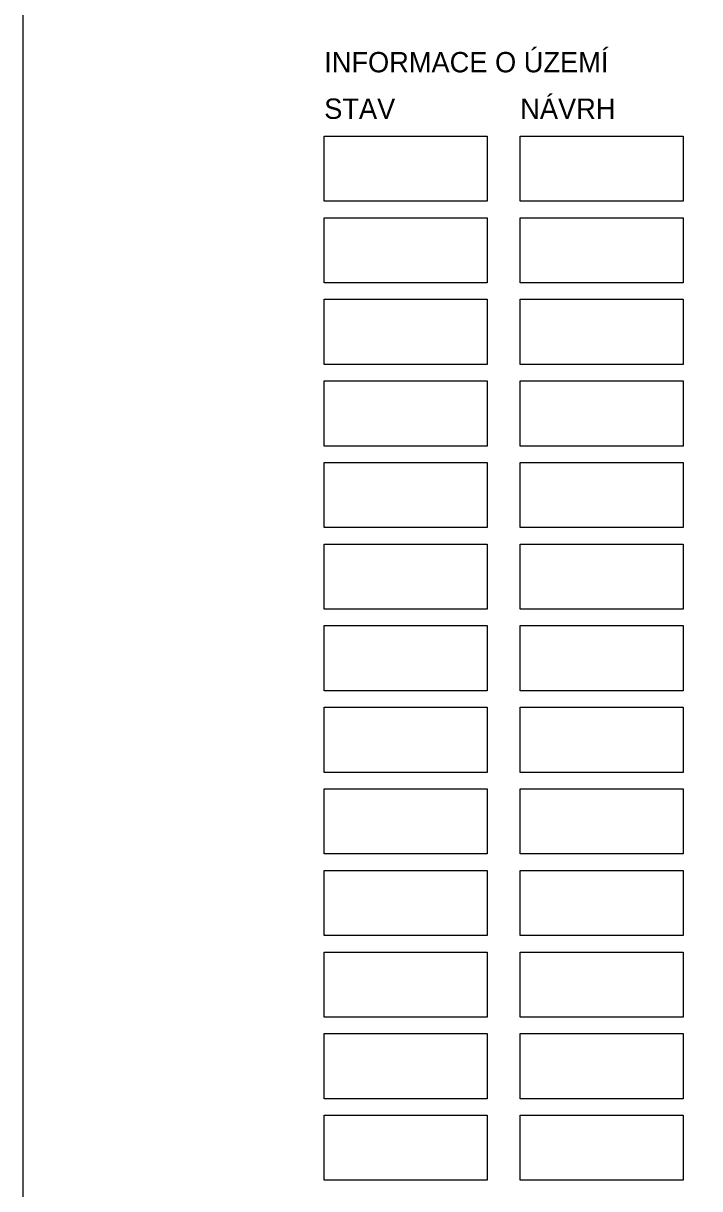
# Model space of a CAD drawing. Extents: x -443494 to -430443, y -1146902 to -1140081.
# Drawn here: x -436490 to -436058, y -1142374 to -1141630 of the extents above; entities that cross this region are included whole.
import ezdxf

# ---------------------------------------------------------------- set-up
doc = ezdxf.new("R2010")
doc.units = 0
doc.layers.add('Vrstva 1', color=7, linetype='Continuous')

msp = doc.modelspace()

# ---------------------------------------------------------------- linework, layer by layer
at = {"layer": 'Vrstva 1'}
for points in [[(-433990.008, -1140080.76), (-433990.008, -1143080.76), (-436490.008, -1143080.76), (-436490.008, -1140080.76)], [(-436297.845, -1141701.798), (-436193.845, -1141701.798), (-436193.845, -1141743.398), (-436297.845, -1141743.398)], [(-436297.845, -1141701.798), (-436193.845, -1141701.798), (-436193.845, -1141743.398), (-436297.845, -1141743.398)], [(-436297.845, -1141701.798), (-436193.845, -1141701.798), (-436193.845, -1141743.398), (-436297.845, -1141743.398)], [(-436297.845, -1141701.798), (-436193.845, -1141701.798), (-436193.845, -1141743.398), (-436297.845, -1141743.398)], [(-436297.845, -1141701.798), (-436193.845, -1141701.798), (-436193.845, -1141743.398), (-436297.845, -1141743.398)], [(-436297.845, -1141701.798), (-436193.845, -1141701.798), (-436193.845, -1141743.398), (-436297.845, -1141743.398)], [(-436297.845, -1141701.798), (-436193.845, -1141701.798), (-436193.845, -1141743.398), (-436297.845, -1141743.398)], [(-436297.845, -1141701.798), (-436193.845, -1141701.798), (-436193.845, -1141743.398), (-436297.845, -1141743.398)], [(-436172.653, -1141701.798), (-436068.653, -1141701.798), (-436068.653, -1141743.398), (-436172.653, -1141743.398)], [(-436172.653, -1141701.798), (-436068.653, -1141701.798), (-436068.653, -1141743.398), (-436172.653, -1141743.398)], [(-436172.653, -1141701.798), (-436068.653, -1141701.798), (-436068.653, -1141743.398), (-436172.653, -1141743.398)], [(-436172.653, -1141701.798), (-436068.653, -1141701.798), (-436068.653, -1141743.398), (-436172.653, -1141743.398)], [(-436172.653, -1141701.798), (-436068.653, -1141701.798), (-436068.653, -1141743.398), (-436172.653, -1141743.398)], [(-436172.653, -1141701.798), (-436068.653, -1141701.798), (-436068.653, -1141743.398), (-436172.653, -1141743.398)], [(-436172.653, -1141701.798), (-436068.653, -1141701.798), (-436068.653, -1141743.398), (-436172.653, -1141743.398)], [(-436172.653, -1141701.798), (-436068.653, -1141701.798), (-436068.653, -1141743.398), (-436172.653, -1141743.398)], [(-436297.845, -1141753.888), (-436193.845, -1141753.888), (-436193.845, -1141795.488), (-436297.845, -1141795.488)], [(-436297.845, -1141753.888), (-436193.845, -1141753.888), (-436193.845, -1141795.488), (-436297.845, -1141795.488)], [(-436297.845, -1141753.888), (-436193.845, -1141753.888), (-436193.845, -1141795.488), (-436297.845, -1141795.488)], [(-436297.845, -1141753.888), (-436193.845, -1141753.888), (-436193.845, -1141795.488), (-436297.845, -1141795.488)], [(-436297.845, -1141753.888), (-436193.845, -1141753.888), (-436193.845, -1141795.488), (-436297.845, -1141795.488)], [(-436297.845, -1141753.888), (-436193.845, -1141753.888), (-436193.845, -1141795.488), (-436297.845, -1141795.488)], [(-436297.845, -1141753.888), (-436193.845, -1141753.888), (-436193.845, -1141795.488), (-436297.845, -1141795.488)], [(-436297.845, -1141753.888), (-436193.845, -1141753.888), (-436193.845, -1141795.488), (-436297.845, -1141795.488)], [(-436172.653, -1141753.888), (-436068.653, -1141753.888), (-436068.653, -1141795.488), (-436172.653, -1141795.488)], [(-436172.653, -1141753.888), (-436068.653, -1141753.888), (-436068.653, -1141795.488), (-436172.653, -1141795.488)], [(-436172.653, -1141753.888), (-436068.653, -1141753.888), (-436068.653, -1141795.488), (-436172.653, -1141795.488)], [(-436172.653, -1141753.888), (-436068.653, -1141753.888), (-436068.653, -1141795.488), (-436172.653, -1141795.488)], [(-436172.653, -1141753.888), (-436068.653, -1141753.888), (-436068.653, -1141795.488), (-436172.653, -1141795.488)], [(-436172.653, -1141753.888), (-436068.653, -1141753.888), (-436068.653, -1141795.488), (-436172.653, -1141795.488)], [(-436172.653, -1141753.888), (-436068.653, -1141753.888), (-436068.653, -1141795.488), (-436172.653, -1141795.488)], [(-436172.653, -1141753.888), (-436068.653, -1141753.888), (-436068.653, -1141795.488), (-436172.653, -1141795.488)], [(-436297.845, -1141805.98), (-436193.845, -1141805.98), (-436193.845, -1141847.58), (-436297.845, -1141847.58)], [(-436297.845, -1141805.98), (-436193.845, -1141805.98), (-436193.845, -1141847.58), (-436297.845, -1141847.58)], [(-436297.845, -1141805.98), (-436193.845, -1141805.98), (-436193.845, -1141847.58), (-436297.845, -1141847.58)], [(-436297.845, -1141805.98), (-436193.845, -1141805.98), (-436193.845, -1141847.58), (-436297.845, -1141847.58)], [(-436297.845, -1141805.98), (-436193.845, -1141805.98), (-436193.845, -1141847.58), (-436297.845, -1141847.58)], [(-436297.845, -1141805.98), (-436193.845, -1141805.98), (-436193.845, -1141847.58), (-436297.845, -1141847.58)], [(-436297.845, -1141805.98), (-436193.845, -1141805.98), (-436193.845, -1141847.58), (-436297.845, -1141847.58)], [(-436297.845, -1141805.98), (-436193.845, -1141805.98), (-436193.845, -1141847.58), (-436297.845, -1141847.58)], [(-436172.653, -1141805.98), (-436068.653, -1141805.98), (-436068.653, -1141847.58), (-436172.653, -1141847.58)], [(-436172.653, -1141805.98), (-436068.653, -1141805.98), (-436068.653, -1141847.58), (-436172.653, -1141847.58)], [(-436172.653, -1141805.98), (-436068.653, -1141805.98), (-436068.653, -1141847.58), (-436172.653, -1141847.58)], [(-436172.653, -1141805.98), (-436068.653, -1141805.98), (-436068.653, -1141847.58), (-436172.653, -1141847.58)], [(-436172.653, -1141805.98), (-436068.653, -1141805.98), (-436068.653, -1141847.58), (-436172.653, -1141847.58)], [(-436172.653, -1141805.98), (-436068.653, -1141805.98), (-436068.653, -1141847.58), (-436172.653, -1141847.58)], [(-436172.653, -1141805.98), (-436068.653, -1141805.98), (-436068.653, -1141847.58), (-436172.653, -1141847.58)], [(-436172.653, -1141805.98), (-436068.653, -1141805.98), (-436068.653, -1141847.58), (-436172.653, -1141847.58)], [(-436297.845, -1141858.072), (-436193.845, -1141858.072), (-436193.845, -1141899.672), (-436297.845, -1141899.672)], [(-436297.845, -1141858.072), (-436193.845, -1141858.072), (-436193.845, -1141899.672), (-436297.845, -1141899.672)], [(-436297.845, -1141858.072), (-436193.845, -1141858.072), (-436193.845, -1141899.672), (-436297.845, -1141899.672)], [(-436297.845, -1141858.072), (-436193.845, -1141858.072), (-436193.845, -1141899.672), (-436297.845, -1141899.672)], [(-436297.845, -1141858.072), (-436193.845, -1141858.072), (-436193.845, -1141899.672), (-436297.845, -1141899.672)], [(-436297.845, -1141858.072), (-436193.845, -1141858.072), (-436193.845, -1141899.672), (-436297.845, -1141899.672)], [(-436297.845, -1141858.072), (-436193.845, -1141858.072), (-436193.845, -1141899.672), (-436297.845, -1141899.672)], [(-436297.845, -1141858.072), (-436193.845, -1141858.072), (-436193.845, -1141899.672), (-436297.845, -1141899.672)], [(-436172.653, -1141858.072), (-436068.653, -1141858.072), (-436068.653, -1141899.672), (-436172.653, -1141899.672)], [(-436172.653, -1141858.072), (-436068.653, -1141858.072), (-436068.653, -1141899.672), (-436172.653, -1141899.672)], [(-436172.653, -1141858.072), (-436068.653, -1141858.072), (-436068.653, -1141899.672), (-436172.653, -1141899.672)], [(-436172.653, -1141858.072), (-436068.653, -1141858.072), (-436068.653, -1141899.672), (-436172.653, -1141899.672)], [(-436172.653, -1141858.072), (-436068.653, -1141858.072), (-436068.653, -1141899.672), (-436172.653, -1141899.672)], [(-436172.653, -1141858.072), (-436068.653, -1141858.072), (-436068.653, -1141899.672), (-436172.653, -1141899.672)], [(-436172.653, -1141858.072), (-436068.653, -1141858.072), (-436068.653, -1141899.672), (-436172.653, -1141899.672)], [(-436172.653, -1141858.072), (-436068.653, -1141858.072), (-436068.653, -1141899.672), (-436172.653, -1141899.672)], [(-436297.845, -1141910.164), (-436193.845, -1141910.164), (-436193.845, -1141951.764), (-436297.845, -1141951.764)], [(-436297.845, -1141910.164), (-436193.845, -1141910.164), (-436193.845, -1141951.764), (-436297.845, -1141951.764)], [(-436297.845, -1141910.164), (-436193.845, -1141910.164), (-436193.845, -1141951.764), (-436297.845, -1141951.764)], [(-436297.845, -1141910.164), (-436193.845, -1141910.164), (-436193.845, -1141951.764), (-436297.845, -1141951.764)], [(-436297.845, -1141910.164), (-436193.845, -1141910.164), (-436193.845, -1141951.764), (-436297.845, -1141951.764)], [(-436297.845, -1141910.164), (-436193.845, -1141910.164), (-436193.845, -1141951.764), (-436297.845, -1141951.764)], [(-436297.845, -1141910.164), (-436193.845, -1141910.164), (-436193.845, -1141951.764), (-436297.845, -1141951.764)], [(-436297.845, -1141910.164), (-436193.845, -1141910.164), (-436193.845, -1141951.764), (-436297.845, -1141951.764)], [(-436172.653, -1141910.164), (-436068.653, -1141910.164), (-436068.653, -1141951.764), (-436172.653, -1141951.764)], [(-436172.653, -1141910.164), (-436068.653, -1141910.164), (-436068.653, -1141951.764), (-436172.653, -1141951.764)], [(-436172.653, -1141910.164), (-436068.653, -1141910.164), (-436068.653, -1141951.764), (-436172.653, -1141951.764)], [(-436172.653, -1141910.164), (-436068.653, -1141910.164), (-436068.653, -1141951.764), (-436172.653, -1141951.764)], [(-436172.653, -1141910.164), (-436068.653, -1141910.164), (-436068.653, -1141951.764), (-436172.653, -1141951.764)], [(-436172.653, -1141910.164), (-436068.653, -1141910.164), (-436068.653, -1141951.764), (-436172.653, -1141951.764)], [(-436172.653, -1141910.164), (-436068.653, -1141910.164), (-436068.653, -1141951.764), (-436172.653, -1141951.764)], [(-436172.653, -1141910.164), (-436068.653, -1141910.164), (-436068.653, -1141951.764), (-436172.653, -1141951.764)], [(-436297.845, -1141962.254), (-436193.845, -1141962.254), (-436193.845, -1142003.854), (-436297.845, -1142003.854)], [(-436297.845, -1141962.254), (-436193.845, -1141962.254), (-436193.845, -1142003.854), (-436297.845, -1142003.854)], [(-436297.845, -1141962.254), (-436193.845, -1141962.254), (-436193.845, -1142003.854), (-436297.845, -1142003.854)], [(-436297.845, -1141962.254), (-436193.845, -1141962.254), (-436193.845, -1142003.854), (-436297.845, -1142003.854)], [(-436297.845, -1141962.254), (-436193.845, -1141962.254), (-436193.845, -1142003.854), (-436297.845, -1142003.854)], [(-436297.845, -1141962.254), (-436193.845, -1141962.254), (-436193.845, -1142003.854), (-436297.845, -1142003.854)], [(-436297.845, -1141962.254), (-436193.845, -1141962.254), (-436193.845, -1142003.854), (-436297.845, -1142003.854)], [(-436297.845, -1141962.254), (-436193.845, -1141962.254), (-436193.845, -1142003.854), (-436297.845, -1142003.854)], [(-436172.653, -1141962.254), (-436068.653, -1141962.254), (-436068.653, -1142003.854), (-436172.653, -1142003.854)], [(-436172.653, -1141962.254), (-436068.653, -1141962.254), (-436068.653, -1142003.854), (-436172.653, -1142003.854)], [(-436172.653, -1141962.254), (-436068.653, -1141962.254), (-436068.653, -1142003.854), (-436172.653, -1142003.854)], [(-436172.653, -1141962.254), (-436068.653, -1141962.254), (-436068.653, -1142003.854), (-436172.653, -1142003.854)], [(-436172.653, -1141962.254), (-436068.653, -1141962.254), (-436068.653, -1142003.854), (-436172.653, -1142003.854)], [(-436172.653, -1141962.254), (-436068.653, -1141962.254), (-436068.653, -1142003.854), (-436172.653, -1142003.854)], [(-436172.653, -1141962.254), (-436068.653, -1141962.254), (-436068.653, -1142003.854), (-436172.653, -1142003.854)], [(-436172.653, -1141962.254), (-436068.653, -1141962.254), (-436068.653, -1142003.854), (-436172.653, -1142003.854)], [(-436297.845, -1142014.346), (-436193.845, -1142014.346), (-436193.845, -1142055.946), (-436297.845, -1142055.946)], [(-436297.845, -1142014.346), (-436193.845, -1142014.346), (-436193.845, -1142055.946), (-436297.845, -1142055.946)], [(-436297.845, -1142014.346), (-436193.845, -1142014.346), (-436193.845, -1142055.946), (-436297.845, -1142055.946)], [(-436297.845, -1142014.346), (-436193.845, -1142014.346), (-436193.845, -1142055.946), (-436297.845, -1142055.946)], [(-436297.845, -1142014.346), (-436193.845, -1142014.346), (-436193.845, -1142055.946), (-436297.845, -1142055.946)], [(-436297.845, -1142014.346), (-436193.845, -1142014.346), (-436193.845, -1142055.946), (-436297.845, -1142055.946)], [(-436297.845, -1142014.346), (-436193.845, -1142014.346), (-436193.845, -1142055.946), (-436297.845, -1142055.946)], [(-436297.845, -1142014.346), (-436193.845, -1142014.346), (-436193.845, -1142055.946), (-436297.845, -1142055.946)], [(-436172.653, -1142014.346), (-436068.653, -1142014.346), (-436068.653, -1142055.946), (-436172.653, -1142055.946)], [(-436172.653, -1142014.346), (-436068.653, -1142014.346), (-436068.653, -1142055.946), (-436172.653, -1142055.946)], [(-436172.653, -1142014.346), (-436068.653, -1142014.346), (-436068.653, -1142055.946), (-436172.653, -1142055.946)], [(-436172.653, -1142014.346), (-436068.653, -1142014.346), (-436068.653, -1142055.946), (-436172.653, -1142055.946)], [(-436172.653, -1142014.346), (-436068.653, -1142014.346), (-436068.653, -1142055.946), (-436172.653, -1142055.946)], [(-436172.653, -1142014.346), (-436068.653, -1142014.346), (-436068.653, -1142055.946), (-436172.653, -1142055.946)], [(-436172.653, -1142014.346), (-436068.653, -1142014.346), (-436068.653, -1142055.946), (-436172.653, -1142055.946)], [(-436172.653, -1142014.346), (-436068.653, -1142014.346), (-436068.653, -1142055.946), (-436172.653, -1142055.946)], [(-436297.845, -1142066.438), (-436193.845, -1142066.438), (-436193.845, -1142108.038), (-436297.845, -1142108.038)], [(-436297.845, -1142066.438), (-436193.845, -1142066.438), (-436193.845, -1142108.038), (-436297.845, -1142108.038)], [(-436297.845, -1142066.438), (-436193.845, -1142066.438), (-436193.845, -1142108.038), (-436297.845, -1142108.038)], [(-436297.845, -1142066.438), (-436193.845, -1142066.438), (-436193.845, -1142108.038), (-436297.845, -1142108.038)], [(-436297.845, -1142066.438), (-436193.845, -1142066.438), (-436193.845, -1142108.038), (-436297.845, -1142108.038)], [(-436297.845, -1142066.438), (-436193.845, -1142066.438), (-436193.845, -1142108.038), (-436297.845, -1142108.038)], [(-436297.845, -1142066.438), (-436193.845, -1142066.438), (-436193.845, -1142108.038), (-436297.845, -1142108.038)], [(-436297.845, -1142066.438), (-436193.845, -1142066.438), (-436193.845, -1142108.038), (-436297.845, -1142108.038)], [(-436172.653, -1142066.438), (-436068.653, -1142066.438), (-436068.653, -1142108.038), (-436172.653, -1142108.038)], [(-436172.653, -1142066.438), (-436068.653, -1142066.438), (-436068.653, -1142108.038), (-436172.653, -1142108.038)], [(-436172.653, -1142066.438), (-436068.653, -1142066.438), (-436068.653, -1142108.038), (-436172.653, -1142108.038)], [(-436172.653, -1142066.438), (-436068.653, -1142066.438), (-436068.653, -1142108.038), (-436172.653, -1142108.038)], [(-436172.653, -1142066.438), (-436068.653, -1142066.438), (-436068.653, -1142108.038), (-436172.653, -1142108.038)], [(-436172.653, -1142066.438), (-436068.653, -1142066.438), (-436068.653, -1142108.038), (-436172.653, -1142108.038)], [(-436172.653, -1142066.438), (-436068.653, -1142066.438), (-436068.653, -1142108.038), (-436172.653, -1142108.038)], [(-436172.653, -1142066.438), (-436068.653, -1142066.438), (-436068.653, -1142108.038), (-436172.653, -1142108.038)], [(-436297.845, -1142118.53), (-436193.845, -1142118.53), (-436193.845, -1142160.13), (-436297.845, -1142160.13)], [(-436297.845, -1142118.53), (-436193.845, -1142118.53), (-436193.845, -1142160.13), (-436297.845, -1142160.13)], [(-436297.845, -1142118.53), (-436193.845, -1142118.53), (-436193.845, -1142160.13), (-436297.845, -1142160.13)], [(-436297.845, -1142118.53), (-436193.845, -1142118.53), (-436193.845, -1142160.13), (-436297.845, -1142160.13)], [(-436297.845, -1142118.53), (-436193.845, -1142118.53), (-436193.845, -1142160.13), (-436297.845, -1142160.13)], [(-436297.845, -1142118.53), (-436193.845, -1142118.53), (-436193.845, -1142160.13), (-436297.845, -1142160.13)], [(-436297.845, -1142118.53), (-436193.845, -1142118.53), (-436193.845, -1142160.13), (-436297.845, -1142160.13)], [(-436297.845, -1142118.53), (-436193.845, -1142118.53), (-436193.845, -1142160.13), (-436297.845, -1142160.13)], [(-436172.653, -1142118.53), (-436068.653, -1142118.53), (-436068.653, -1142160.13), (-436172.653, -1142160.13)], [(-436172.653, -1142118.53), (-436068.653, -1142118.53), (-436068.653, -1142160.13), (-436172.653, -1142160.13)], [(-436172.653, -1142118.53), (-436068.653, -1142118.53), (-436068.653, -1142160.13), (-436172.653, -1142160.13)], [(-436172.653, -1142118.53), (-436068.653, -1142118.53), (-436068.653, -1142160.13), (-436172.653, -1142160.13)], [(-436172.653, -1142118.53), (-436068.653, -1142118.53), (-436068.653, -1142160.13), (-436172.653, -1142160.13)], [(-436172.653, -1142118.53), (-436068.653, -1142118.53), (-436068.653, -1142160.13), (-436172.653, -1142160.13)], [(-436172.653, -1142118.53), (-436068.653, -1142118.53), (-436068.653, -1142160.13), (-436172.653, -1142160.13)], [(-436172.653, -1142118.53), (-436068.653, -1142118.53), (-436068.653, -1142160.13), (-436172.653, -1142160.13)], [(-436297.845, -1142170.62), (-436193.845, -1142170.62), (-436193.845, -1142212.22), (-436297.845, -1142212.22)], [(-436297.845, -1142170.62), (-436193.845, -1142170.62), (-436193.845, -1142212.22), (-436297.845, -1142212.22)], [(-436297.845, -1142170.62), (-436193.845, -1142170.62), (-436193.845, -1142212.22), (-436297.845, -1142212.22)], [(-436297.845, -1142170.62), (-436193.845, -1142170.62), (-436193.845, -1142212.22), (-436297.845, -1142212.22)], [(-436297.845, -1142170.62), (-436193.845, -1142170.62), (-436193.845, -1142212.22), (-436297.845, -1142212.22)], [(-436297.845, -1142170.62), (-436193.845, -1142170.62), (-436193.845, -1142212.22), (-436297.845, -1142212.22)], [(-436297.845, -1142170.62), (-436193.845, -1142170.62), (-436193.845, -1142212.22), (-436297.845, -1142212.22)], [(-436297.845, -1142170.62), (-436193.845, -1142170.62), (-436193.845, -1142212.22), (-436297.845, -1142212.22)], [(-436172.653, -1142170.62), (-436068.653, -1142170.62), (-436068.653, -1142212.22), (-436172.653, -1142212.22)], [(-436172.653, -1142170.62), (-436068.653, -1142170.62), (-436068.653, -1142212.22), (-436172.653, -1142212.22)], [(-436172.653, -1142170.62), (-436068.653, -1142170.62), (-436068.653, -1142212.22), (-436172.653, -1142212.22)], [(-436172.653, -1142170.62), (-436068.653, -1142170.62), (-436068.653, -1142212.22), (-436172.653, -1142212.22)], [(-436172.653, -1142170.62), (-436068.653, -1142170.62), (-436068.653, -1142212.22), (-436172.653, -1142212.22)], [(-436172.653, -1142170.62), (-436068.653, -1142170.62), (-436068.653, -1142212.22), (-436172.653, -1142212.22)], [(-436172.653, -1142170.62), (-436068.653, -1142170.62), (-436068.653, -1142212.22), (-436172.653, -1142212.22)], [(-436172.653, -1142170.62), (-436068.653, -1142170.62), (-436068.653, -1142212.22), (-436172.653, -1142212.22)], [(-436297.845, -1142222.712), (-436193.845, -1142222.712), (-436193.845, -1142264.312), (-436297.845, -1142264.312)], [(-436297.845, -1142222.712), (-436193.845, -1142222.712), (-436193.845, -1142264.312), (-436297.845, -1142264.312)], [(-436297.845, -1142222.712), (-436193.845, -1142222.712), (-436193.845, -1142264.312), (-436297.845, -1142264.312)], [(-436297.845, -1142222.712), (-436193.845, -1142222.712), (-436193.845, -1142264.312), (-436297.845, -1142264.312)], [(-436297.845, -1142222.712), (-436193.845, -1142222.712), (-436193.845, -1142264.312), (-436297.845, -1142264.312)], [(-436297.845, -1142222.712), (-436193.845, -1142222.712), (-436193.845, -1142264.312), (-436297.845, -1142264.312)], [(-436297.845, -1142222.712), (-436193.845, -1142222.712), (-436193.845, -1142264.312), (-436297.845, -1142264.312)], [(-436297.845, -1142222.712), (-436193.845, -1142222.712), (-436193.845, -1142264.312), (-436297.845, -1142264.312)], [(-436172.653, -1142222.712), (-436068.653, -1142222.712), (-436068.653, -1142264.312), (-436172.653, -1142264.312)], [(-436172.653, -1142222.712), (-436068.653, -1142222.712), (-436068.653, -1142264.312), (-436172.653, -1142264.312)], [(-436172.653, -1142222.712), (-436068.653, -1142222.712), (-436068.653, -1142264.312), (-436172.653, -1142264.312)], [(-436172.653, -1142222.712), (-436068.653, -1142222.712), (-436068.653, -1142264.312), (-436172.653, -1142264.312)], [(-436172.653, -1142222.712), (-436068.653, -1142222.712), (-436068.653, -1142264.312), (-436172.653, -1142264.312)], [(-436172.653, -1142222.712), (-436068.653, -1142222.712), (-436068.653, -1142264.312), (-436172.653, -1142264.312)], [(-436172.653, -1142222.712), (-436068.653, -1142222.712), (-436068.653, -1142264.312), (-436172.653, -1142264.312)], [(-436172.653, -1142222.712), (-436068.653, -1142222.712), (-436068.653, -1142264.312), (-436172.653, -1142264.312)], [(-436297.845, -1142274.804), (-436193.845, -1142274.804), (-436193.845, -1142316.404), (-436297.845, -1142316.404)], [(-436297.845, -1142274.804), (-436193.845, -1142274.804), (-436193.845, -1142316.404), (-436297.845, -1142316.404)], [(-436297.845, -1142274.804), (-436193.845, -1142274.804), (-436193.845, -1142316.404), (-436297.845, -1142316.404)], [(-436297.845, -1142274.804), (-436193.845, -1142274.804), (-436193.845, -1142316.404), (-436297.845, -1142316.404)], [(-436297.845, -1142274.804), (-436193.845, -1142274.804), (-436193.845, -1142316.404), (-436297.845, -1142316.404)], [(-436297.845, -1142274.804), (-436193.845, -1142274.804), (-436193.845, -1142316.404), (-436297.845, -1142316.404)], [(-436297.845, -1142274.804), (-436193.845, -1142274.804), (-436193.845, -1142316.404), (-436297.845, -1142316.404)], [(-436297.845, -1142274.804), (-436193.845, -1142274.804), (-436193.845, -1142316.404), (-436297.845, -1142316.404)], [(-436172.653, -1142274.804), (-436068.653, -1142274.804), (-436068.653, -1142316.404), (-436172.653, -1142316.404)], [(-436172.653, -1142274.804), (-436068.653, -1142274.804), (-436068.653, -1142316.404), (-436172.653, -1142316.404)], [(-436172.653, -1142274.804), (-436068.653, -1142274.804), (-436068.653, -1142316.404), (-436172.653, -1142316.404)], [(-436172.653, -1142274.804), (-436068.653, -1142274.804), (-436068.653, -1142316.404), (-436172.653, -1142316.404)], [(-436172.653, -1142274.804), (-436068.653, -1142274.804), (-436068.653, -1142316.404), (-436172.653, -1142316.404)], [(-436172.653, -1142274.804), (-436068.653, -1142274.804), (-436068.653, -1142316.404), (-436172.653, -1142316.404)], [(-436172.653, -1142274.804), (-436068.653, -1142274.804), (-436068.653, -1142316.404), (-436172.653, -1142316.404)], [(-436172.653, -1142274.804), (-436068.653, -1142274.804), (-436068.653, -1142316.404), (-436172.653, -1142316.404)], [(-436297.845, -1142326.894), (-436193.845, -1142326.894), (-436193.845, -1142368.494), (-436297.845, -1142368.494)], [(-436297.845, -1142326.894), (-436193.845, -1142326.894), (-436193.845, -1142368.494), (-436297.845, -1142368.494)], [(-436297.845, -1142326.894), (-436193.845, -1142326.894), (-436193.845, -1142368.494), (-436297.845, -1142368.494)], [(-436297.845, -1142326.894), (-436193.845, -1142326.894), (-436193.845, -1142368.494), (-436297.845, -1142368.494)], [(-436297.845, -1142326.894), (-436193.845, -1142326.894), (-436193.845, -1142368.494), (-436297.845, -1142368.494)], [(-436297.845, -1142326.894), (-436193.845, -1142326.894), (-436193.845, -1142368.494), (-436297.845, -1142368.494)], [(-436297.845, -1142326.894), (-436193.845, -1142326.894), (-436193.845, -1142368.494), (-436297.845, -1142368.494)], [(-436297.845, -1142326.894), (-436193.845, -1142326.894), (-436193.845, -1142368.494), (-436297.845, -1142368.494)], [(-436172.653, -1142326.894), (-436068.653, -1142326.894), (-436068.653, -1142368.494), (-436172.653, -1142368.494)], [(-436172.653, -1142326.894), (-436068.653, -1142326.894), (-436068.653, -1142368.494), (-436172.653, -1142368.494)], [(-436172.653, -1142326.894), (-436068.653, -1142326.894), (-436068.653, -1142368.494), (-436172.653, -1142368.494)], [(-436172.653, -1142326.894), (-436068.653, -1142326.894), (-436068.653, -1142368.494), (-436172.653, -1142368.494)], [(-436172.653, -1142326.894), (-436068.653, -1142326.894), (-436068.653, -1142368.494), (-436172.653, -1142368.494)], [(-436172.653, -1142326.894), (-436068.653, -1142326.894), (-436068.653, -1142368.494), (-436172.653, -1142368.494)], [(-436172.653, -1142326.894), (-436068.653, -1142326.894), (-436068.653, -1142368.494), (-436172.653, -1142368.494)], [(-436172.653, -1142326.894), (-436068.653, -1142326.894), (-436068.653, -1142368.494), (-436172.653, -1142368.494)]]:
    msp.add_lwpolyline(points, close=True, dxfattribs=at)

# ---------------------------------------------------------------- texts
for s, p in [('INFORMACE O ÚZEMÍ', (-436297.845, -1141661.086)), ('INFORMACE O ÚZEMÍ', (-436297.845, -1141661.086)), ('INFORMACE O ÚZEMÍ', (-436297.845, -1141661.086)), ('INFORMACE O ÚZEMÍ', (-436297.845, -1141661.086)), ('STAV', (-436297.845, -1141690.786)), ('STAV', (-436297.845, -1141690.786)), ('STAV', (-436297.845, -1141690.786)), ('STAV', (-436297.845, -1141690.786)), ('STAV', (-436297.845, -1141690.786)), ('STAV', (-436297.845, -1141690.786)), ('STAV', (-436297.845, -1141690.786)), ('STAV', (-436297.845, -1141690.786)), ('NÁVRH', (-436172.653, -1141690.786)), ('NÁVRH', (-436172.653, -1141690.786)), ('NÁVRH', (-436172.653, -1141690.786)), ('NÁVRH', (-436172.653, -1141690.786)), ('NÁVRH', (-436172.653, -1141690.786)), ('NÁVRH', (-436172.653, -1141690.786)), ('NÁVRH', (-436172.653, -1141690.786)), ('NÁVRH', (-436172.653, -1141690.786))]:
    msp.add_text(s, height=12.9974, dxfattribs=at).set_placement(p)

doc.saveas('drawing.dxf')
